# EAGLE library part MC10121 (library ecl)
4-wide "or-and/or-and-invert" Gate
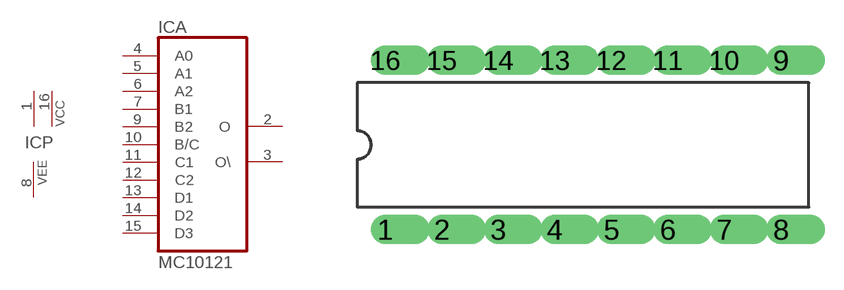
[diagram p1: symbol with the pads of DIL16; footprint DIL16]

Designator prefix IC; gates A=MC10121 P=2VCC1VEE

## MC10121  [DIL16]
1  P:VCC  pwr
2  A:O  out
3  A:O\  out
4  A:A0  in
5  A:A1  in
6  A:A2  in
7  A:B1  in
8  P:VEE  pwr
9  A:B2  in
10  A:B/C  in
11  A:C1  in
12  A:C2  in
13  A:D1  in
14  A:D2  in
15  A:D3  in
16  P:VCC  pwr

## Footprint DIL16 (pad centres in mm)
drill 0.813 offset: 1 -8.89,-3.81; 2 -6.35,-3.81; 3 -3.81,-3.81; 4 -1.27,-3.81; 5 1.27,-3.81; 6 3.81,-3.81; 7 6.35,-3.81; 8 8.89,-3.81; 9 8.89,3.81; 10 6.35,3.81; 11 3.81,3.81; 12 1.27,3.81; 13 -1.27,3.81; 14 -3.81,3.81; 15 -6.35,3.81; 16 -8.89,3.81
